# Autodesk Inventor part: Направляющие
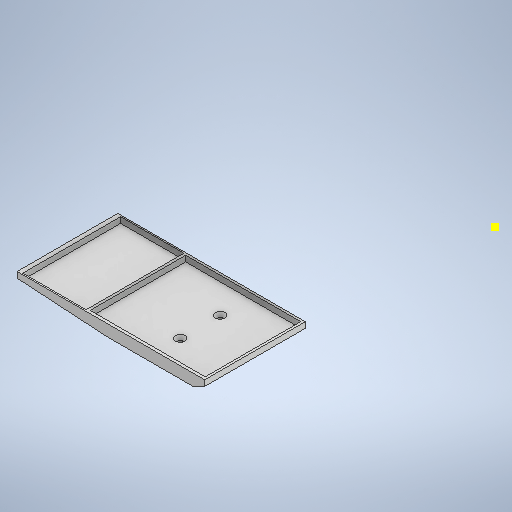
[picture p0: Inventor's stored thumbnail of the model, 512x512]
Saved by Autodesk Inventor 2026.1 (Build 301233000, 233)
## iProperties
Created: 2025-12
Part Number: Направляющие
Material: Типовые
Document SubType Name: Modeling
Designer: Yury Melnikov
Density: 1 g/cm^3
Appearance: По умолчанию
Author: Yury Melnikov
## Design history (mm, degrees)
sketch "Эскиз1"
  geometry: L1 (0, 0)-(16, 0); L2 (16, 0)-(16, -200); L3 (16, -200)-(0, -200); L4 (0, -200)-(0, 0); 1 further point
  constraints: 8 end point, 2 parallel, 1 coincident, 1 horizontal, 1 perpendicular
  dimensions: "d0" = 16 distance of L2.end L3.end; "d1" = 200 distance of L1.end L2.end
extrude "Выдавливание1" new body sketch "Эскиз1" distance "d2" = 200; taper "d3" = 0 deg
sketch "Эскиз2"
  geometry: 1 further point
sketch "Эскиз3"
  geometry: L1 (0, 0)-(0, -200) reference; L2 (-16, -200)-(-16, 0) reference; L3 (-28.3, -33.725)-(12.3, -10.284); L4 (12.3, -10.284)-(12.3, -57.165); L5 (12.3, -57.165)-(-28.3, -33.725); C1 r 12.3 at (-28.3, -33.725); C2 r 12.3 at (12.3, -10.284); C3 r 12.3 at (12.3, -57.165); 1 further point
  constraints: 6 end point, 3 centre point, 3 coincident, 2 equal radius, 2 tangent, 1 vertical, 7 other
  dimensions: "d4" = 24.6 diameter of C2
extrude "Выдавливание2" new body sketch "Эскиз3" distance "d5" = 11; taper "d6" = 0 deg
sketch "Эскиз4"
  geometry: C1 r 12.3 at (0, 0) reference; C2 r 12.3 at (40.6, 23.44) reference; C3 r 12.3 at (40.6, -23.44) reference; C4 r 4 at (0, 0); C5 r 4 at (40.6, 23.44); C6 r 4 at (40.6, -23.44); 1 further point
  constraints: 3 centre point, 3 coincident, 2 equal radius
  dimensions: "d7" = 8 diameter of C5
extrude "Выдавливание3" join sketch "Эскиз4" distance "d8" = 6; taper "d9" = 0 deg
sketch "Эскиз5"
  geometry: L1 (-6.15, 10.652)-(34.45, 34.093); L2 (52.9, 23.44)-(52.9, -23.44); L3 (34.45, -34.093)-(-6.15, -10.652); A1 r 12.3 centre (40.6, -23.44) between (34.45, -34.093) and (52.9, -23.44) reference; A2 r 12.3 centre (40.6, 23.44) between (52.9, 23.44) and (34.45, 34.093) reference; A3 r 12.3 centre (0, 0) between (-6.15, -10.652) and (-6.15, 10.652) reference; 1 further point
  constraints: 6 end point, 6 point on circle, 6 tangent
extrude "Выдавливание4" new body sketch "Эскиз5" distance "d10" = 4; taper "d11" = 0 deg
sketch "Эскиз6"
  geometry: L1 (0, 0)-(40.6, 23.44); L2 (40.6, 23.44)-(40.6, -23.44); L3 (40.6, -23.44)-(0, 0); L4 (35.6, 23.44)-(2.5, 4.33); L5 (2.5, -4.33)-(35.6, -23.44); L6 (43.1, -19.11)-(43.1, 19.11); L7 (38.1, 19.11)-(5, 0); L8 (5, 0)-(38.1, -19.11); L9 (38.1, -19.11)-(38.1, 19.11); C1 r 12.3 at (40.6, 23.44) reference; C2 r 12.3 at (40.6, -23.44) reference; C3 r 12.3 at (0, 0) reference; C4 r 1.6 at (0, 0); C5 r 1.6 at (40.6, 23.44); C6 r 1.6 at (40.6, -23.44); A1 r 5 centre (40.6, 23.44) between (43.1, 19.11) and (35.6, 23.44); A2 r 5 centre (0, 0) between (2.5, 4.33) and (2.5, -4.33); A3 r 5 centre (40.6, -23.44) between (35.6, -23.44) and (43.1, -19.11); 3 further points
  constraints: 18 end point, 8 coincident, 6 centre point, 6 point on circle, 2 equal length, 2 equal radius, 2 parallel, 13 other
  dimensions: "d12" = 2.5 distance between parallel lines of L1 L7; "d13" = 2.5 distance between parallel lines of L1 L4 (= d12); "d14" = 3.2 diameter of C4 (derived); "d15" = 3.2 diameter of C5 (derived); "d16" = 3.2 diameter of C6
extrude "Выдавливание5" join sketch "Эскиз6" distance "d17" = 5; taper "d18" = 0 deg
sketch "Эскиз7"
  geometry: C1 r 1.6 at (40.6, 23.44) reference; C2 r 1.6 at (0, 0) reference; C3 r 1.6 at (40.6, -23.44) reference; 1 further point
  node "Спроецированная петля5"
  node "Спроецированная петля6"
  node "Спроецированная петля7"
fillet "Сопряжение1" dims "d19" = 5
chamfer "Фаска1" distance "d20" = 2; stored, may be unused: second distance "d21" = 2, angle "d22" = 45 deg
extrude "Выдавливание6" cut sketch "Эскиз7" distance "d23" = 5; taper "d24" = 0 deg
sketch "Эскиз8"
  geometry: L1 (4.478, 5.472)-(33.622, 22.298) reference; L2 (43.1, 16.826)-(43.1, -16.826) reference; L3 (33.622, -22.298)-(4.478, -5.472) reference; L4 (34.45, 34.093)-(-6.15, 10.652) reference; L5 (-6.15, -10.652)-(34.45, -34.093) reference; L6 (52.9, -23.44)-(52.9, 23.44) reference; L7 (30, -82.992)-(34, -82.992); L8 (28.3, 33.725)-(28.3, -166.275) reference; L9 (142.9, -11.74)-(142.9, -38.74); L10 (139.9, -41.74)-(46.638, -41.74); L11 (35.571, -38.399)-(-6.806, -10.245); L12 (34.45, 34.093)-(-6.15, 10.652) reference; L13 (-6.15, 10.652)-(32.359, 35.974); L14 (141.217, -9.045)-(47.187, 36.917); A1 r 5 centre (1.978, -9.802) between (4.478, -5.472) and (0.989, -4.901) reference; A2 r 5 centre (0, 0) between (0.989, 4.901) and (0.989, -4.901) reference; A3 r 5 centre (1.978, 9.802) between (0.989, 4.901) and (4.478, 5.472) reference; A4 r 5 centre (31.122, 26.628) between (33.622, 22.298) and (35.861, 25.034) reference; A5 r 5 centre (40.6, 23.44) between (44.35, 20.133) and (35.861, 25.034) reference; A6 r 5 centre (48.1, 16.826) between (44.35, 20.133) and (43.1, 16.826) reference; A7 r 5 centre (48.1, -16.826) between (43.1, -16.826) and (44.35, -20.133) reference; A8 r 5 centre (40.6, -23.44) between (35.861, -25.034) and (44.35, -20.133) reference; A9 r 5 centre (31.122, -26.628) between (35.861, -25.034) and (33.622, -22.298) reference; A10 r 12.3 centre (40.6, 23.44) between (52.9, 23.44) and (34.45, 34.093) reference; A11 r 12.3 centre (0, 0) between (-6.15, 10.652) and (-6.15, -10.652) reference; A12 r 12.3 centre (40.6, -23.44) between (34.45, -34.093) and (52.9, -23.44) reference; A13 r 12.3 centre (0, 0) between (-6.15, 10.652) and (-6.15, -10.652) reference; A14 r 12.3 centre (40.6, 23.44) between (52.9, 23.44) and (34.45, 34.093) reference; A15 r 20 centre (46.638, -21.74) between (35.571, -38.399) and (46.638, -41.74); A16 r 3 centre (139.9, -11.74) between (142.9, -11.74) and (141.217, -9.045); A17 r 3 centre (139.9, -38.74) between (139.9, -41.74) and (142.9, -38.74); A18 r 15 centre (40.6, 23.44) between (26.541, 18.21) and (28.3, 14.855); A19 r 15 centre (40.6, 23.44) between (47.187, 36.917) and (32.359, 35.974); 6 further points
  constraints: 14 point on circle, 12 end point, 9 tangent, 7 point on line, 5 centre point, 1 coincident, 1 horizontal, 1 vertical, 1 vertical alignment
  dimensions: "d40" = 8 distance of point (142.9, -33.74) point (142.9, -41.74); "d41" = 90 distance from line of point (142.9, -41.74) L6; "d42" = 6 distance edge to line of A12 L10; "d43" = 20 radius of A15; "d44" = 3 radius of A16; "d45" = 3 radius of A17 (= d44); "d61" = 15 radius of A19; "d62" = 30 distance from line of L10 L9.start
extrude "Выдавливание7" new body sketch "Эскиз8" distance "d26" = 4; taper "d27" = 0 deg
node "РабПлоскость1"
sketch "Эскиз11"
  geometry: L1 (-6.806, -10.245)-(35.571, -38.399) reference; L2 (46.638, -41.74)-(139.9, -41.74) reference; L3 (142.9, -38.74)-(142.9, -11.74) reference; L4 (33.622, -22.298)-(4.478, -5.472) reference; L5 (4.478, 5.472)-(33.622, 22.298) reference; L6 (43.1, 16.826)-(43.1, -16.826) reference; L7 (30.967, -35.34)-(142.9, -35.34); L8 (37.92, -39.74)-(142.728, -39.74); L9 (77.92, -35.34)-(97.92, -35.34); L10 (97.92, -35.34)-(97.92, -39.74); L11 (97.92, -39.74)-(77.92, -39.74); L12 (77.92, -39.74)-(77.92, -35.34); L13 (112.9, -35.34)-(132.9, -35.34); L14 (132.9, -35.34)-(132.9, -39.74); L15 (132.9, -39.74)-(112.9, -39.74); L16 (112.9, -39.74)-(112.9, -35.34); L17 (32.359, 35.974)-(-6.15, 10.652) reference; L18 (141.217, -9.045)-(47.187, 36.917) reference; A1 r 12.3 centre (0, 0) between (-6.15, 10.652) and (-6.806, -10.245) reference; A2 r 20 centre (46.638, -21.74) between (35.571, -38.399) and (46.638, -41.74) reference; A3 r 3 centre (139.9, -38.74) between (139.9, -41.74) and (142.9, -38.74) reference; A4 r 3 centre (139.9, -11.74) between (142.9, -11.74) and (141.217, -9.045) reference; A5 r 5 centre (1.978, -9.802) between (4.478, -5.472) and (0.989, -4.901) reference; A6 r 5 centre (0, 0) between (0.989, 4.901) and (0.989, -4.901) reference; A7 r 5 centre (1.978, 9.802) between (0.989, 4.901) and (4.478, 5.472) reference; A8 r 5 centre (31.122, 26.628) between (33.622, 22.298) and (35.861, 25.034) reference; A9 r 5 centre (40.6, 23.44) between (44.35, 20.133) and (35.861, 25.034) reference; A10 r 5 centre (48.1, 16.826) between (44.35, 20.133) and (43.1, 16.826) reference; A11 r 5 centre (48.1, -16.826) between (43.1, -16.826) and (44.35, -20.133) reference; A12 r 5 centre (40.6, -23.44) between (35.861, -25.034) and (44.35, -20.133) reference; A13 r 5 centre (31.122, -26.628) between (35.861, -25.034) and (33.622, -22.298) reference; A14 r 15 centre (40.6, 23.44) between (47.187, 36.917) and (32.359, 35.974) reference; 1 further point
  constraints: 20 end point, 6 point on line, 4 horizontal, 4 parallel, 2 perpendicular, 2 point on circle
  dimensions: "d47" = 4.4 distance between parallel lines of L8 L7; "d48" = 2 distance between parallel lines of L2 L8; "d49" = 20 distance between parallel lines of L12 L10; "d50" = 20 distance between parallel lines of L14 L16; "d51" = 10 distance between parallel lines of L14 L3; "d52" = 40 distance from line of L8.start L12
extrude "Выдавливание9" cut sketch "Эскиз11" distance "d53" = 4; taper "d54" = 0 deg
chamfer "Фаска2" distance "d55" = 2; stored, may be unused: second distance "d56" = 2, angle "d57" = 45 deg
fillet "Сопряжение2" dims "d58" = 1
sketch "Эскиз14"
  geometry: L1 (-142.9, -35.34)-(-67.92, -35.34); L2 (-67.92, -35.34)-(-67.92, -39.74); L3 (-67.92, -39.74)-(-142.9, -39.74); L4 (-142.9, -39.74)-(-142.9, -35.34); L5 (-97.92, -35.34)-(-77.92, -35.34) reference; L6 (-77.92, -39.74)-(-97.92, -39.74) reference; L7 (-77.92, -35.34)-(-77.92, -39.74) reference; L8 (-142.9, -38.74)-(-142.9, -11.74) reference; 2 further points
  constraints: 8 end point, 3 collinear, 2 parallel, 1 horizontal, 1 midpoint, 1 perpendicular
  dimensions: "d63" = 10 distance from line of L2 point (-77.92, -37.54)
extrude "Выдавливание10" new body sketch "Эскиз14" distance "d65" = 228; taper "d66" = 0 deg
sketch "Эскиз15"
  geometry: L1 (3, 15)-(3, 11.4); L2 (3, 11.4)-(8, 6.4); L3 (8, 6.4)-(20, 6.4); L4 (20, 6.4)-(20, 3.4); L5 (20, 3.4)-(0, 3.4); L6 (0, 3.4)-(228, 3.4) reference; L7 (0, 3.4)-(0, 23); L8 (0, 23)-(20, 23); L9 (3, 15)-(8, 20); L10 (8, 20)-(20, 20); L11 (20, 20)-(20, 23); 5 further points; 1 other entity
  constraints: 20 end point, 4 equal length, 3 vertical, 2 horizontal, 2 perpendicular, 1 collinear, 1 other
  dimensions: "d67" = 3 distance of L3.end L4.end; "d76" = 3 distance between parallel lines of L7 L1 (derived); "d77" = 20 distance of L4.end L5.end; "d78" = 135 deg angle of L10 L9; "d79" = 5 horizontal distance of L1.start L9.end; "d108" = 4 distance of L7.end point (0, 27)
extrude "Выдавливание11" new body sketch "Эскиз15" stored distance "d69" = 128; taper "d70" = 0 deg
sketch "Эскиз16"
  geometry: L1 (67.92, -35.34)-(142.9, -35.34) reference; L2 (67.92, -39.74)-(67.92, -35.34) reference; L3 (142.9, -39.74)-(67.92, -39.74) reference; L4 (142.9, -35.34)-(142.9, -39.74) reference; L5 (132.9, -35.34)-(132.9, -39.74) reference; L6 (132.9, -39.74)-(112.9, -39.74) reference; L7 (112.9, -39.74)-(112.9, -35.34) reference; L8 (112.9, -35.34)-(132.9, -35.34) reference; L9 (97.92, -35.34)-(97.92, -39.74) reference; L10 (97.92, -39.74)-(77.92, -39.74) reference; L11 (77.92, -39.74)-(77.92, -35.34) reference; L12 (77.92, -35.34)-(97.92, -35.34) reference; L13 (-6.806, -10.245)-(35.571, -38.399) reference; L14 (46.638, -41.74)-(139.9, -41.74) reference; L15 (142.9, -38.74)-(142.9, -11.74) reference; L16 (141.217, -9.045)-(47.187, 36.917) reference; L17 (32.359, 35.974)-(-6.15, 10.652) reference; L18 (33.622, -22.298)-(4.478, -5.472) reference; L19 (4.478, 5.472)-(33.622, 22.298) reference; L20 (43.1, 16.826)-(43.1, -16.826) reference; L21 (97.72, -39.54)-(97.72, -35.54); L22 (97.72, -35.54)-(78.12, -35.54); L23 (78.12, -35.54)-(78.12, -39.54); L24 (78.12, -39.54)-(97.72, -39.54); L25 (113.1, -35.54)-(113.1, -39.54); L26 (113.1, -39.54)-(132.7, -39.54); L27 (132.7, -39.54)-(132.7, -35.54); L28 (132.7, -35.54)-(113.1, -35.54); A1 r 12.3 centre (0, 0) between (-6.15, 10.652) and (-6.806, -10.245) reference; A2 r 20 centre (46.638, -21.74) between (35.571, -38.399) and (46.638, -41.74) reference; A3 r 3 centre (139.9, -38.74) between (139.9, -41.74) and (142.9, -38.74) reference; A4 r 3 centre (139.9, -11.74) between (142.9, -11.74) and (141.217, -9.045) reference; A5 r 15 centre (40.6, 23.44) between (47.187, 36.917) and (32.359, 35.974) reference; A6 r 5 centre (1.978, -9.802) between (4.478, -5.472) and (0.989, -4.901) reference; A7 r 5 centre (0, 0) between (0.989, 4.901) and (0.989, -4.901) reference; A8 r 5 centre (1.978, 9.802) between (0.989, 4.901) and (4.478, 5.472) reference; A9 r 5 centre (31.122, 26.628) between (33.622, 22.298) and (35.861, 25.034) reference; A10 r 5 centre (40.6, 23.44) between (44.35, 20.133) and (35.861, 25.034) reference; A11 r 5 centre (48.1, 16.826) between (44.35, 20.133) and (43.1, 16.826) reference; A12 r 5 centre (48.1, -16.826) between (43.1, -16.826) and (44.35, -20.133) reference; A13 r 5 centre (40.6, -23.44) between (35.861, -25.034) and (44.35, -20.133) reference; A14 r 5 centre (31.122, -26.628) between (35.861, -25.034) and (33.622, -22.298) reference; 1 further point
  constraints: 16 end point, 6 other
  dimensions: "d71" = 0.2 distance between parallel lines of L9 L21; "d72" = 0.2 distance between parallel lines of L7 L25
extrude "Выдавливание12" join sketch "Эскиз16" stored distance "d73" = 228; taper "d74" = 0 deg
node "РабПлоскость2"
mirror "Зеркальное отражение2"
sketch "Эскиз17"
  geometry: L1 (15.8, 7.674)-(15.8, 4.326); L2 (15.8, 4.326)-(12.9, 2.651); L3 (12.9, 2.651)-(10, 4.326); L4 (10, 4.326)-(10, 7.674); L5 (10, 7.674)-(12.9, 9.349); L6 (12.9, 9.349)-(15.8, 7.674); L7 (12.9, 0.342)-(17.8, 3.171); L8 (17.8, 3.171)-(17.8, 8.829); L9 (17.8, 8.829)-(12.9, 11.658); L10 (12.9, 11.658)-(8, 8.829); L11 (8, 8.829)-(8, 3.171); L12 (8, 3.171)-(12.9, 0.342); L13 (0, 0)-(0, 12) reference; L14 (0, 17)-(74.98, 17) reference; L15 (32.59, 8.829)-(32.59, 3.171); L16 (34.59, 4.326)-(34.59, 7.674); L17 (37.49, 2.651)-(34.59, 4.326); L18 (37.49, 11.658)-(32.59, 8.829); L19 (32.59, 3.171)-(37.49, 0.342); L20 (34.59, 7.674)-(37.49, 9.349); L21 (40.39, 4.326)-(37.49, 2.651); L22 (40.39, 7.674)-(40.39, 4.326); L23 (37.49, 9.349)-(40.39, 7.674); L24 (37.49, 0.342)-(42.39, 3.171); L25 (42.39, 3.171)-(42.39, 8.829); L26 (42.39, 8.829)-(37.49, 11.658); L27 (57.18, 8.829)-(57.18, 3.171); L28 (59.18, 4.326)-(59.18, 7.674); L29 (62.08, 2.651)-(59.18, 4.326); L30 (62.08, 11.658)-(57.18, 8.829); L31 (57.18, 3.171)-(62.08, 0.342); L32 (59.18, 7.674)-(62.08, 9.349); L33 (64.98, 4.326)-(62.08, 2.651); L34 (64.98, 7.674)-(64.98, 4.326); L35 (62.08, 9.349)-(64.98, 7.674); L36 (62.08, 0.342)-(66.98, 3.171); L37 (66.98, 3.171)-(66.98, 8.829); L38 (66.98, 8.829)-(62.08, 11.658); L39 (74.98, 0)-(74.98, 12) reference; 11 further points
  constraints: 72 end point, 5 midpoint, 1 horizontal, 1 horizontal alignment, 1 vertical, 70 other
  dimensions: "d80" = 5.8 distance between parallel lines of L4 L1; "d82" = 2 distance from line of point (15.35, 1.756) L2; "d85" = 24.58984 distance of L10.end L15.start (derived); "d90" = 8 distance from line of point (8, 6) L13; "d157" = 8 distance of point (66.98, 6) point (74.98, 6) (derived)
extrude "Выдавливание13" join sketch "Эскиз17" distance "d92" = 2.5; taper "d93" = 0 deg
fillet "Сопряжение3" dims "d94" = 2
chamfer "Фаска3" distance "d95" = 0.8; stored, may be unused: second distance "d96" = 2, angle "d97" = 45 deg
sketch "Эскиз18"
  geometry: L1 (5.8, 3.349)-(2.9, 5.023) reference; L2 (2.9, 5.023)-(0, 3.349) reference; L3 (0, 3.349)-(0, 0) reference; L4 (0, 0)-(2.9, -1.674) reference; L5 (2.9, -1.674)-(5.8, 0) reference; L6 (5.8, 0)-(5.8, 3.349) reference; L7 (5.8, 3.349)-(5.8, 0) reference; L8 (-10, 7.674)-(64.98, 7.674) reference; C1 r 1.65 at (2.9, 1.674); C2 r 1.65 at (27.49, 1.674); C3 r 1.65 at (52.08, 1.674); C4 r 1.65 at (76.67, 1.674); 3 further points
  constraints: 4 centre point, 2 vertical alignment, 1 horizontal, 1 horizontal alignment, 1 midpoint, 6 other
  dimensions: "d98" = 3.3 diameter of C1; "d101" = 24.58984 distance of C1.centre C2.centre (derived)
extrude "Выдавливание14" cut sketch "Эскиз18" distance "d106" = 10; taper "d107" = 0 deg
node "РабПлоскость3"
mirror "Зеркальное отражение3"
sketch "Эскиз19"
  geometry: L1 (-97.72, -35.54)-(-97.72, -39.54) reference; L2 (-78.12, -35.54)-(-97.72, -35.54) reference; L3 (-78.12, -39.54)-(-78.12, -35.54) reference; L4 (-97.72, -39.54)-(-78.12, -39.54) reference; L5 (-77.92, -11.54)-(-97.92, -11.54); L6 (-97.92, -11.54)-(-97.92, -15.74); L7 (-97.92, -15.74)-(-77.92, -15.74); L8 (-77.92, -15.74)-(-77.92, -11.54); L9 (-142.9, -15.74)-(-67.92, -15.74) reference; L10 (-112.9, -11.54)-(-132.9, -11.54); L11 (-132.9, -11.54)-(-132.9, -15.74); L12 (-132.9, -15.74)-(-112.9, -15.74); L13 (-112.9, -15.74)-(-112.9, -11.54); L14 (-112.9, -39.74)-(-112.9, -35.34) reference; L15 (-132.9, -35.34)-(-132.9, -39.74) reference; L16 (-77.92, -39.74)-(-77.92, -35.34) reference; L17 (-97.92, -35.34)-(-97.92, -39.74) reference; 3 further points
  constraints: 16 end point, 6 collinear, 4 parallel, 2 horizontal, 2 perpendicular
  dimensions: "d109" = 4.2 distance of L7.end L5.start; "d110" = 4.2 distance of L12.end L10.start
extrude "Выдавливание15" cut sketch "Эскиз19" distance "d111" = 10; taper "d112" = 0 deg
sketch "Эскиз20"
  geometry: L1 (39.69, -35)-(35.29, -35); L2 (35.29, -35)-(35.29, -75); L3 (35.29, -75)-(39.69, -75); L4 (39.69, -75)-(39.69, -35); L5 (39.69, -94)-(35.29, -94); L6 (35.29, -94)-(35.29, -134); L7 (35.29, -134)-(39.69, -134); L8 (39.69, -134)-(39.69, -94); L9 (39.69, -153)-(35.29, -153); L10 (35.29, -153)-(35.29, -193); L11 (35.29, -193)-(39.69, -193); L12 (39.69, -193)-(39.69, -153); L13 (0, -20)-(74.98, -20) reference; L14 (0, 0)-(74.98, 0) reference; L15 (74.98, -228)-(0, -228) reference; 3 further points
  constraints: 24 end point, 2 midpoint, 2 parallel, 1 collinear, 1 horizontal, 1 perpendicular, 1 vertical, 1 vertical alignment, 15 other
  dimensions: "d113" = 4.4 distance of L1.start L1.end; "d116" = 59 distance of L1.start L5.start (derived); "d122" = 35 distance between parallel lines of L14 L1; "d123" = 35 distance from line of L15 L11.end; "d124" = 40 distance of L3.end L1.start
extrude "Выдавливание16" cut sketch "Эскиз20" distance "d125" = 10; taper "d126" = 0 deg
sketch "Эскиз21"
  geometry: L1 (39.69, -193)-(35.29, -193) reference; L2 (35.29, -193)-(35.29, -153) reference; L3 (35.29, -153)-(39.69, -153) reference; L4 (39.69, -153)-(39.69, -193) reference; L5 (39.69, -134)-(35.29, -134) reference; L6 (35.29, -134)-(35.29, -94) reference; L7 (35.29, -94)-(39.69, -94) reference; L8 (39.69, -94)-(39.69, -134) reference; L9 (39.69, -75)-(35.29, -75) reference; L10 (35.29, -75)-(35.29, -35) reference; L11 (35.29, -35)-(39.69, -35) reference; L12 (39.69, -35)-(39.69, -75) reference; L13 (74.98, 0)-(0, 0) reference; L14 (0, 0)-(0, -228) reference; L15 (74.98, -228)-(0, -228) reference; L16 (74.98, 0)-(74.98, -228) reference; L17 (39.59, -74.9)-(35.39, -74.9); L18 (35.39, -74.9)-(35.39, -35.1); L19 (35.39, -35.1)-(39.59, -35.1); L20 (39.59, -35.1)-(39.59, -74.9); L21 (39.59, -133.9)-(35.39, -133.9); L22 (35.39, -133.9)-(35.39, -94.1); L23 (35.39, -94.1)-(39.59, -94.1); L24 (39.59, -94.1)-(39.59, -133.9); L25 (39.59, -192.9)-(35.39, -192.9); L26 (35.39, -192.9)-(35.39, -153.1); L27 (35.39, -153.1)-(39.59, -153.1); L28 (39.59, -153.1)-(39.59, -192.9); L29 (0, -20)-(74.98, -20) reference; L30 (39.59, -20)-(35.39, -20); L31 (35.39, -20)-(35.39, -208); L32 (35.39, -208)-(39.59, -208); L33 (39.59, -208)-(39.59, -20); C1 r 1.65 at (62.08, -14) reference; C2 r 1.65 at (37.49, -14) reference; C3 r 1.65 at (12.9, -14) reference; 1 further point
  constraints: 32 end point, 2 collinear, 2 parallel, 1 horizontal, 1 perpendicular, 1 point on line, 9 other
  dimensions: "d127" = 0.1 distance between parallel lines of L12 L20; "d128" = 0.1 distance between parallel lines of L8 L24; "d129" = 0.1 distance between parallel lines of L4 L28; "d130" = 20 distance between parallel lines of L15 L32
extrude "Выдавливание17" new body sketch "Эскиз21" stored distance "d131" = 10; taper "d132" = 0 deg
sketch "Эскиз22"
  geometry: L1 (39.59, -20)-(35.39, -20); L2 (35.39, -20)-(35.39, -208); L3 (35.39, -208)-(39.59, -208); L4 (39.59, -208)-(39.59, -20); L5 (0, -20)-(74.98, -20) reference; L6 (74.98, -228)-(0, -228) reference; 3 further points
  constraints: 8 end point, 2 parallel, 2 point on line, 1 collinear, 1 horizontal, 1 perpendicular
  dimensions: "d133" = 20 distance between parallel lines of L6 L3
extrude "Выдавливание18" join sketch "Эскиз22" stored distance "d134" = 10; taper "d135" = 0 deg
node "РабПлоскость4"
mirror "Зеркальное отражение4"
sketch "Эскиз23"
  geometry: L1 (-112.9, -15.74)-(-132.9, -15.74) reference; L2 (-132.9, -15.74)-(-132.9, -11.54) reference; L3 (-132.9, -11.54)-(-112.9, -11.54) reference; L4 (-112.9, -11.54)-(-112.9, -15.74) reference; L5 (-77.92, -15.74)-(-97.92, -15.74) reference; L6 (-97.92, -15.74)-(-97.92, -11.54) reference; L7 (-97.92, -11.54)-(-77.92, -11.54) reference; L8 (-77.92, -11.54)-(-77.92, -15.74) reference; L9 (-132.9, -39.74)-(-132.9, -35.34) reference; L10 (-132.9, -35.34)-(-112.9, -35.34) reference; L11 (-112.9, -35.34)-(-112.9, -39.74) reference; L12 (-112.9, -39.74)-(-132.9, -39.74) reference; L13 (-97.92, -39.74)-(-97.92, -35.34) reference; L14 (-97.92, -35.34)-(-77.92, -35.34) reference; L15 (-77.92, -35.34)-(-77.92, -39.74) reference; L16 (-77.92, -39.74)-(-97.92, -39.74) reference; L17 (-32.359, 35.974)-(6.15, 10.652) reference; L18 (-141.217, -9.045)-(-47.187, 36.917) reference; L19 (-142.9, -38.74)-(-142.9, -11.74) reference; L20 (-46.638, -41.74)-(-139.9, -41.74) reference; L21 (6.806, -10.245)-(-35.571, -38.399) reference; L22 (-33.622, -22.298)-(-4.478, -5.472) reference; L23 (-43.1, 16.826)-(-43.1, -16.826) reference; L24 (-4.478, 5.472)-(-33.622, 22.298) reference; C1 r 1.65 at (-45.173, -38.366); C2 r 1.65 at (-57.173, -38.366); C3 r 12.3 at (-40.6, -23.44) reference; C4 r 3.31 at (-45.173, -38.366); A1 r 12.3 centre (0, 0) between (6.806, -10.245) and (6.15, 10.652) reference; A2 r 15 centre (-40.6, 23.44) between (-32.359, 35.974) and (-47.187, 36.917) reference; A3 r 3 centre (-139.9, -11.74) between (-141.217, -9.045) and (-142.9, -11.74) reference; A4 r 3 centre (-139.9, -38.74) between (-142.9, -38.74) and (-139.9, -41.74) reference; A5 r 20 centre (-46.638, -21.74) between (-46.638, -41.74) and (-35.571, -38.399) reference; A6 r 5 centre (-31.122, -26.628) between (-33.622, -22.298) and (-35.861, -25.034) reference; A7 r 5 centre (-40.6, -23.44) between (-44.35, -20.133) and (-35.861, -25.034) reference; A8 r 5 centre (-48.1, -16.826) between (-44.35, -20.133) and (-43.1, -16.826) reference; A9 r 5 centre (-48.1, 16.826) between (-43.1, 16.826) and (-44.35, 20.133) reference; A10 r 5 centre (-40.6, 23.44) between (-35.861, 25.034) and (-44.35, 20.133) reference; A11 r 5 centre (-31.122, 26.628) between (-35.861, 25.034) and (-33.622, 22.298) reference; A12 r 5 centre (-1.978, 9.802) between (-4.478, 5.472) and (-0.989, 4.901) reference; A13 r 5 centre (0, 0) between (-0.989, -4.901) and (-0.989, 4.901) reference; A14 r 5 centre (-1.978, -9.802) between (-0.989, -4.901) and (-4.478, -5.472) reference; 1 further point
  constraints: 3 centre point, 2 tangent, 1 coincident, 1 equal radius, 1 horizontal alignment
  dimensions: "d136" = 3.3 diameter of C2; "d137" = 12 distance of C1.centre C2.centre
extrude "Выдавливание19" cut sketch "Эскиз23" distance "d138" = 10; taper "d139" = 0 deg
sketch "Эскиз24"
  geometry: C1 r 4 at (0, 0) reference; C2 r 4 at (40.6, 23.44) reference; C3 r 4 at (40.6, -23.44) reference; C4 r 2.5 at (0, 0); C5 r 2.5 at (40.6, 23.44); C6 r 2.5 at (40.6, -23.44); C7 r 5.5 at (40.6, 23.44); C8 r 5.5 at (0, 0); C9 r 5.5 at (40.6, -23.44); 1 further point
  constraints: 6 centre point, 2 coincident, 1 concentric
  dimensions: "d140" = 5 diameter of C4; "d141" = 5 diameter of C5; "d142" = 5 diameter of C6; "d143" = 3 radial gap between concentric circles of C5 C7; "d144" = 3 radial gap between concentric circles of C4 C8; "d145" = 3 radial gap between concentric circles of C6 C9
extrude "Выдавливание20" join sketch "Эскиз24" stored distance "d146" = 10; taper "d147" = 0 deg
sketch "Эскиз25"
  geometry: C1 r 5.5 at (0, 0) reference; C2 r 5.5 at (40.6, -23.44) reference; C3 r 5.5 at (40.6, 23.44) reference; C4 r 2.5 at (0, 0); C5 r 2.5 at (40.6, 23.44); C6 r 2.5 at (40.6, -23.44); 1 further point
  constraints: 3 centre point, 3 coincident, 2 equal radius
  dimensions: "d148" = 5 diameter of C4
extrude "Выдавливание21" cut sketch "Эскиз25" distance "d149" = 30; taper "d150" = 0 deg
chamfer "Фаска4" distance "d151" = 4; stored, may be unused: second distance "d152" = 2, angle "d153" = 45 deg
sketch "Эскиз26"
  geometry: L1 (39.69, -193)-(35.29, -193) reference; L2 (35.29, -193)-(35.29, -153) reference; L3 (35.29, -153)-(39.69, -153) reference; L4 (39.69, -153)-(39.69, -193) reference; L5 (39.69, -134)-(35.29, -134) reference; L6 (35.29, -134)-(35.29, -94) reference; L7 (35.29, -94)-(39.69, -94) reference; L8 (39.69, -94)-(39.69, -134) reference; L9 (39.69, -75)-(35.29, -75) reference; L10 (35.29, -75)-(35.29, -35) reference; L11 (35.29, -35)-(39.69, -35) reference; L12 (39.69, -35)-(39.69, -75) reference; L13 (74.98, 0)-(0, 0) reference; L14 (0, 0)-(0, -228) reference; L15 (74.98, -228)-(0, -228) reference; L16 (74.98, 0)-(74.98, -228) reference; L17 (74.98, 0)-(64.78, 0); L18 (64.78, 0)-(64.78, -5); L19 (64.78, -5)-(74.98, -5); L20 (74.98, -5)-(74.98, 0); L21 (64.78, 0)-(64.78, 4) reference; L22 (74.98, -228)-(64.78, -228); L23 (64.78, -228)-(64.78, -223); L24 (64.78, -223)-(74.98, -223); L25 (74.98, -223)-(74.98, -228); L26 (64.78, -228)-(64.78, -232) reference; C1 r 1.65 at (62.08, -14) reference; C2 r 1.65 at (37.49, -14) reference; C3 r 1.65 at (12.9, -14) reference; 5 further points
  constraints: 16 end point, 4 parallel, 3 collinear, 2 horizontal, 2 perpendicular
  dimensions: "d154" = 5 distance of L18.end L17.end
extrude "Выдавливание22" cut sketch "Эскиз26" distance "d155" = 30; taper "d156" = 0 deg
feature "Толщина1" dims "d158" = 0.2, "d159" = 0.2
sketch "Эскиз27"
  geometry: L1 (-16.475, -18.345)-(-16.475, 18.345); L2 (-16.475, 18.345)-(-48.25, 0); L3 (-48.25, 0)-(-16.475, -18.345); L4 (-52.9, -23.44)-(-52.9, 23.44) reference; L5 (6.15, -10.652)-(-34.45, -34.093) reference; L6 (-34.45, 34.093)-(6.15, 10.652) reference; C1 r 1.65 at (-16.475, 18.345); C2 r 1.65 at (-16.475, -18.345); C3 r 1.65 at (-48.25, 0); 1 further point
  constraints: 6 end point, 3 centre point, 2 equal length, 2 equal radius, 1 vertical
  dimensions: "d160" = 3.3 diameter of C2; "d161" = 3 distance edge to line of C3 L4; "d162" = 3 distance edge to line of C2 L5; "d163" = 3 distance edge to line of C1 L6
extrude "Выдавливание23" cut sketch "Эскиз27" distance "d164" = 20; taper "d165" = 0 deg
chamfer "Фаска5" distance "d166" = 2; stored, may be unused: second distance "d167" = 2, angle "d168" = 45 deg
sketch "Эскиз28"
  geometry: L1 (14.517, 4.6)-(16.133, 1.8); L2 (16.133, 1.8)-(14.517, -1); L3 (14.517, -1)-(11.283, -1); L4 (11.283, -1)-(9.667, 1.8); L5 (9.667, 1.8)-(11.283, 4.6); L6 (11.283, 4.6)-(14.517, 4.6); L7 (0, 0)-(0, 3.6) reference; L8 (13.9, 6.1)-(11.9, 6.1) reference; L9 (39.106, 4.6)-(40.723, 1.8); L10 (40.723, 1.8)-(39.106, -1); L11 (39.106, -1)-(35.873, -1); L12 (35.873, -1)-(34.257, 1.8); L13 (34.257, 1.8)-(35.873, 4.6); L14 (35.873, 4.6)-(39.106, 4.6); L15 (63.696, 4.6)-(65.313, 1.8); L16 (65.313, 1.8)-(63.696, -1); L17 (63.696, -1)-(60.463, -1); L18 (60.463, -1)-(58.847, 1.8); L19 (58.847, 1.8)-(60.463, 4.6); L20 (60.463, 4.6)-(63.696, 4.6); L21 (38.49, 6.1)-(36.49, 6.1) reference; L22 (17.981, 1.8)-(15.44, 6.2); L23 (15.44, 6.2)-(10.36, 6.2); L24 (10.36, 6.2)-(7.819, 1.8); L25 (7.819, 1.8)-(10.36, -2.6); L26 (10.36, -2.6)-(15.44, -2.6); L27 (15.44, -2.6)-(17.981, 1.8); L28 (34.949, 6.2)-(32.409, 1.8); L29 (32.409, 1.8)-(34.949, -2.6); L30 (34.949, -2.6)-(40.03, -2.6); L31 (40.03, -2.6)-(42.571, 1.8); L32 (42.571, 1.8)-(40.03, 6.2); L33 (40.03, 6.2)-(34.949, 6.2); L34 (59.539, 6.2)-(56.999, 1.8); L35 (56.999, 1.8)-(59.539, -2.6); L36 (59.539, -2.6)-(64.62, -2.6); L37 (64.62, -2.6)-(67.16, 1.8); L38 (67.16, 1.8)-(64.62, 6.2); L39 (64.62, 6.2)-(59.539, 6.2); 7 further points
  constraints: 72 end point, 3 midpoint, 2 horizontal, 2 vertical alignment, 1 collinear, 1 horizontal alignment, 53 other
  dimensions: "d169" = 5.6 distance between parallel lines of L3 L6; "d172" = 24.58984 distance of point (12.9, 1.8) point (37.49, 1.8) (derived); "d177" = 1.6 distance between parallel lines of L1 L22; "d178" = 1.6 distance between parallel lines of L13 L28; "d179" = 1.6 distance between parallel lines of L19 L34
extrude "Выдавливание24" join sketch "Эскиз28" distance "d180" = 3; taper "d181" = 0 deg
sketch "Эскиз29"
  geometry: L1 (15.44, 6.2)-(10.36, 6.2) reference; L2 (10.36, 6.2)-(7.819, 1.8) reference; L3 (7.819, 1.8)-(10.36, -2.6) reference; L4 (10.36, -2.6)-(15.44, -2.6) reference; L5 (15.44, -2.6)-(17.981, 1.8) reference; L6 (17.981, 1.8)-(15.44, 6.2) reference; L7 (14.517, 4.6)-(16.133, 1.8) reference; L8 (16.133, 1.8)-(14.517, -1) reference; L9 (14.517, -1)-(11.283, -1) reference; L10 (11.283, -1)-(9.667, 1.8) reference; L11 (9.667, 1.8)-(11.283, 4.6) reference; L12 (11.283, 4.6)-(14.517, 4.6) reference; L13 (32.409, 1.8)-(34.949, -2.6) reference; L14 (34.949, -2.6)-(40.03, -2.6) reference; L15 (40.03, -2.6)-(42.571, 1.8) reference; L16 (42.571, 1.8)-(40.03, 6.2) reference; L17 (40.03, 6.2)-(34.949, 6.2) reference; L18 (34.949, 6.2)-(32.409, 1.8) reference; L19 (39.106, 4.6)-(40.723, 1.8) reference; L20 (40.723, 1.8)-(39.106, -1) reference; L21 (39.106, -1)-(35.873, -1) reference; L22 (35.873, -1)-(34.257, 1.8) reference; L23 (34.257, 1.8)-(35.873, 4.6) reference; L24 (35.873, 4.6)-(39.106, 4.6) reference; L25 (56.999, 1.8)-(59.539, -2.6) reference; L26 (59.539, -2.6)-(64.62, -2.6) reference; L27 (64.62, -2.6)-(67.16, 1.8) reference; L28 (67.16, 1.8)-(64.62, 6.2) reference; L29 (64.62, 6.2)-(59.539, 6.2) reference; L30 (59.539, 6.2)-(56.999, 1.8) reference; L31 (63.696, 4.6)-(65.313, 1.8) reference; L32 (65.313, 1.8)-(63.696, -1) reference; L33 (63.696, -1)-(60.463, -1) reference; L34 (60.463, -1)-(58.847, 1.8) reference; L35 (58.847, 1.8)-(60.463, 4.6) reference; L36 (60.463, 4.6)-(63.696, 4.6) reference; 1 further point
extrude "Выдавливание25" cut sketch "Эскиз29" stored distance "d182" = 3; taper "d183" = 0 deg
sketch "Эскиз30"
  geometry: L1 (-24.59, 5.6)-(-26.206, 2.8) reference; L2 (-24.59, 0)-(-26.206, 2.8) reference; L3 (-21.357, 0)-(-24.59, 0) reference; L4 (-21.357, 0)-(-19.74, 2.8) reference; L5 (-19.74, 2.8)-(-21.357, 5.6) reference; L6 (-24.59, 5.6)-(-21.357, 5.6) reference; L7 (0, 5.6)-(-1.617, 2.8) reference; L8 (0, 0)-(-1.617, 2.8) reference; L9 (3.233, 0)-(0, 0) reference; L10 (3.233, 0)-(4.85, 2.8) reference; L11 (4.85, 2.8)-(3.233, 5.6) reference; L12 (0, 5.6)-(3.233, 5.6) reference; L13 (24.59, 5.6)-(22.973, 2.8) reference; L14 (24.59, 0)-(22.973, 2.8) reference; L15 (27.823, 0)-(24.59, 0) reference; L16 (27.823, 0)-(29.44, 2.8) reference; L17 (29.44, 2.8)-(27.823, 5.6) reference; L18 (24.59, 5.6)-(27.823, 5.6) reference; L19 (24.59, 5.6)-(27.823, 5.6) reference; L20 (0, 5.6)-(3.233, 5.6) reference; L21 (-24.59, 5.6)-(-21.357, 5.6) reference; C1 r 1.65 at (-22.973, 2.8); C2 r 1.65 at (1.617, 2.8); C3 r 1.65 at (26.206, 2.8); 4 further points
  constraints: 3 centre point, 3 horizontal alignment, 3 midpoint, 3 vertical alignment, 2 equal radius
  dimensions: "d184" = 3.3 diameter of C2
extrude "Выдавливание26" cut sketch "Эскиз30" distance "d185" = 10; taper "d186" = 0 deg
chamfer "Фаска6" distance "d187" = 0.7; stored, may be unused: second distance "d188" = 2, angle "d189" = 45 deg
fillet "Сопряжение4" dims "d190" = 1
sketch "Эскиз31"
  geometry: L1 (19.6, -236)-(0, -236) reference; L2 (0, -232)-(0, -236) reference; L3 (19.6, -232)-(0, -232) reference; L4 (19.6, -232)-(19.6, -236) reference; L5 (54.58, -236)-(34.98, -236) reference; L6 (34.98, -232)-(34.98, -236) reference; L7 (54.58, -232)-(34.98, -232) reference; L8 (54.58, -232)-(54.58, -236) reference; L9 (19.6, 0)-(0, 0) reference; L10 (19.6, -4)-(19.6, 0) reference; L11 (0, -4)-(19.6, -4) reference; L12 (0, -4)-(0, 0) reference; L13 (54.58, 0)-(34.98, 0) reference; L14 (54.58, -4)-(54.58, 0) reference; L15 (34.98, -4)-(54.58, -4) reference; L16 (34.98, -4)-(34.98, 0) reference; 1 further point
extrude "Выдавливание27" join sketch "Эскиз31" stored distance "d191" = 10; taper "d192" = 0 deg
mirror "Зеркальное отражение5"
chamfer "Фаска7" distance "d193" = 0.5; stored, may be unused: second distance "d194" = 2, angle "d195" = 45 deg
sketch "Эскиз32"
  geometry: L1 (-52.9, -23.44)-(-51.9, -23.44) reference; L2 (-52.9, -23.44)-(-52.9, 23.44) reference; L3 (6.15, -10.652)-(-34.45, -34.093) reference; L4 (-34.45, 34.093)-(6.15, 10.652) reference; C1 r 3.65 at (-16.475, -18.345) reference; C2 r 1.6 at (-40.6, 23.44) reference; C3 r 1.6 at (-40.6, -23.44) reference; C4 r 1.6 at (0, 0) reference; C5 r 3.65 at (-16.475, 18.345) reference; C6 r 3.65 at (-48.25, 0) reference; A1 r 35 centre (-27.005, 0.107) between (-52.9, -23.44) and (-34.45, -34.093); A2 r 12.3 centre (-40.6, 23.44) between (-34.45, 34.093) and (-52.9, 23.44) reference; A3 r 12.3 centre (-40.6, -23.44) between (-52.9, -23.44) and (-34.45, -34.093) reference; A4 r 12.3 centre (0, 0) between (6.15, -10.652) and (6.15, 10.652) reference; 3 further points
  constraints: 2 point on circle, 1 centre point
  dimensions: "d196" = 35 radius of A1
extrude "Выдавливание28" cut sketch "Эскиз32" distance "d197" = 10; taper "d198" = 0 deg
fillet "Сопряжение5" dims "d199" = 10
chamfer "Фаска8" distance "d200" = 1; stored, may be unused: second distance "d201" = 2, angle "d202" = 45 deg
sketch "Эскиз33"
  geometry: C1 r 1.6 at (-40.6, 23.44) reference; C2 r 1.65 at (-40.6, 23.44); C3 r 4.05 at (-40.6, 23.44); 1 further point
  constraints: 2 centre point, 1 coincident
  dimensions: "d203" = 3.3 diameter of C2; "d204" = 2.4 radial gap between concentric circles of C2 C3
extrude "Выдавливание29" new body sketch "Эскиз33" distance "d205" = 5; taper "d206" = 0 deg
sketch "Эскиз34"
  geometry: C1 r 1.65 at (0, 0) reference; C2 r 2.45 at (0, 0); 1 further point
  constraints: 1 centre point
  dimensions: "d207" = 0.8 radial gap between concentric circles of C1 C2
extrude "Выдавливание30" join sketch "Эскиз34" distance "d208" = 1; taper "d209" = 0 deg
chamfer "Фаска10" distance "d213" = 0.5; stored, may be unused: second distance "d214" = 1.6, angle "d215" = 45 deg
sketch "Эскиз35"
  geometry: C1 r 12.3 at (0, 0) reference; C2 r 1.65 at (0, 0); 1 further point
  constraints: 1 centre point, 1 coincident
  dimensions: "d216" = 3.3 diameter of C2
extrude "Выдавливание31" new body sketch "Эскиз35" distance "d217" = 11; taper "d218" = 0 deg
sketch "Эскиз36"
  geometry: L1 (-2.8, -1.617)-(-2.8, 1.617); L2 (-2.8, 1.617)-(0, 3.233); L3 (0, 3.233)-(2.8, 1.617); L4 (2.8, 1.617)-(2.8, -1.617); L5 (2.8, -1.617)-(0, -3.233); L6 (0, -3.233)-(-2.8, -1.617); C1 r 1.65 at (0, 0) reference; 2 further points
  constraints: 12 end point, 1 coincident, 1 vertical, 13 other
  dimensions: "d219" = 5.6 distance between parallel lines of L4 L1
extrude "Выдавливание32" cut sketch "Эскиз36" distance "d220" = 5; taper "d221" = 0 deg
fillet "Сопряжение6" dims "d225" = 1
sketch "Эскиз38"
  geometry: C1 r 1.65 at (0, 0) reference; C2 r 3.9 at (0, 0); 1 further point
  constraints: 1 centre point, 1 coincident
  dimensions: "d230" = 7.8 diameter of C2
extrude "Выдавливание33" cut sketch "Эскиз38" stored distance "d231" = 4; taper "d232" = 0 deg
chamfer "Фаска12" distance "d233" = 0.4; stored, may be unused: second distance "d234" = 1.6, angle "d235" = 45 deg
sketch "Эскиз40"
  geometry: C1 r 1.6 at (0, 0) reference; C2 r 1.6 at (-40.6, -23.44) reference; 3 further points
  constraints: 2 coincident
feature "Массив по эскизу1" sketch "Эскиз40"
sketch "Эскиз41"
  geometry: C1 r 1.6 at (0, 0) reference; C2 r 1.6 at (-40.6, -23.44) reference; 3 further points
  constraints: 2 coincident
feature "Массив по эскизу2" sketch "Эскиз41"
mirror "Зеркальное отражение6"
mirror "Зеркальное отражение7"
mirror "Зеркальное отражение8"
mirror "Зеркальное отражение9"
mirror "Зеркальное отражение10"
node "РабПлоскость6"
mirror "Зеркальное отражение11"
sketch "Эскиз42"
  geometry: L1 (4.2, -55)-(-23.8, -55); L2 (-23.8, -55)-(-23.8, -90.855); L3 (-23.8, -90.855)-(4.2, -90.855); L4 (4.2, -90.855)-(4.2, -55); L5 (-29.8, 0)-(-29.8, -228) reference; L6 (9.89, -75)-(5.49, -75) reference; C1 r 1.75 at (4.2, -55); C2 r 1.75 at (4.2, -90.855); C3 r 1.75 at (-23.8, -55); C4 r 1.75 at (-23.8, -90.855); 1 further point
  constraints: 8 end point, 4 centre point, 2 horizontal, 2 parallel, 1 perpendicular, 1 vertical, 6 other
  dimensions: "d237" = 35.855 distance of L1.end L2.end; "d238" = 28 distance of L1.start L1.end; "d239" = 3.5 diameter of C1; "d240" = 6 distance from line of L5 L1.end; "d241" = 20 distance from line of L1.start L6; "d244" = 35.855 distance of L1.start C2.centre (derived); "d247" = 28 distance of L1.start C3.centre (derived)
extrude "Выдавливание34" cut sketch "Эскиз42" distance "d250" = 10; taper "d251" = 0 deg
chamfer "Фаска13" distance "d252" = 2; stored, may be unused: second distance "d253" = 2, angle "d254" = 45 deg
sketch "Эскиз43"
  geometry: L1 (45.18, -5)-(45.18, -223) reference; L2 (-29.8, 0)-(-29.8, -228) reference; L3 (45.18, -116.855)-(-29.8, -116.855); L4 (-29.8, -116.855)-(-29.8, -227); L5 (-29.8, -227)-(45.18, -227); L6 (45.18, -227)-(45.18, -116.855); L7 (-28.117, -228)-(65.913, -228) reference; C1 r 1.75 at (-23.8, -90.855) reference; 1 further point
  constraints: 8 end point, 2 parallel, 2 point on line, 1 horizontal, 1 perpendicular
  dimensions: "d255" = 1 distance between parallel lines of L7 L5; "d256" = 26 distance from line of C1.centre L3
node "РабПлоскость7"
sketch "Эскиз44"
  geometry: L1 (-52.526, -130.428)-(-106.526, -130.428); L2 (-106.526, -130.428)-(-106.526, -214.428); L3 (-106.526, -214.428)-(-52.526, -214.428); L4 (-52.526, -214.428)-(-52.526, -130.428); L5 (41.041, -116.855)-(41.041, -228); L6 (-28.117, -228)-(65.913, -228) reference; L7 (60.2, -208)-(60.2, -217) reference; L8 (52.474, -130.928)-(-47.526, -130.928); L9 (-47.526, -130.928)-(-47.526, -213.928); L10 (-47.526, -213.928)-(52.474, -213.927); L11 (52.474, -213.927)-(52.474, -130.928); L12 (45.18, -116.855)-(54.474, -127.928); L13 (54.474, -127.928)-(54.474, -215.927); L14 (54.474, -215.927)-(45.18, -227); L15 (-108.526, -128.428)-(-108.526, -219.266); L16 (-108.526, -128.428)-(54.474, -128.428); L17 (-108.526, -215.927)-(54.474, -215.927); 6 further points
  constraints: 30 end point, 4 horizontal, 4 midpoint, 4 parallel, 3 point on line, 2 horizontal alignment, 2 perpendicular, 2 vertical, 1 equal length
  dimensions: "d258" = 54 distance of L3.end L2.end; "d259" = 84 distance of L2.end L1.end; "d261" = 100 distance of L10.end L9.end; "d262" = 83 distance of L9.end L8.end; "d264" = 5 distance between parallel lines of L9 L4; "d265" = 2 distance between parallel lines of L13 L11; "d266" = 2 distance from line of L13.end L10; "d268" = 2 distance from line of L1 L15.start; "d290" = 2 distance between parallel lines of L15 L2
feature "Лофт1" sketch "Эскиз44" dims "d269" = 0, "d270" = 90 deg, "d291" = 0, "d292" = 90 deg
sketch "Эскиз45"
  geometry: L1 (84.274, -99.072)-(84.274, -11.573) reference; L2 (-75, -12.822)-(-20, -12.823); L3 (-20, -12.823)-(-20, -97.823); L4 (-20, -97.823)-(-75, -97.823); L5 (-75, -97.823)-(-75, -12.822); L6 (82.274, -13.573)-(-17.726, -13.573); L7 (-17.726, -13.573)-(-17.726, -96.573); L8 (-17.726, -96.573)-(82.274, -96.573); L9 (82.274, -96.573)-(82.274, -13.573); L10 (84.274, -99.072)-(84.274, -11.573) reference; L11 (-78.726, -99.072)-(84.274, -99.072) reference; L12 (-78.726, -11.573)-(-78.726, -99.072) reference; L13 (84.274, -11.573)-(-78.726, -11.573) reference; 7 further points
  constraints: 16 end point, 4 parallel, 3 midpoint, 2 horizontal, 2 horizontal alignment, 2 perpendicular, 1 point on line
  dimensions: "d273" = 55 distance of L3.end L4.end; "d274" = 85 distance of L2.end L3.end; "d276" = 100 distance of L8.end L7.end; "d277" = 83 distance of L7.end L6.end; "d278" = 2 distance between parallel lines of L1 L9
extrude "Выдавливание35" join sketch "Эскиз45" distance "d279" = 5; taper "d280" = 0 deg
sketch "Эскиз46"
  geometry: L1 (82.506, 125.427)-(82.506, 134.427) reference; L2 (82.506, 134.427)-(62.906, 134.427) reference; L3 (62.906, 134.427)-(62.906, 130.428) reference; L4 (47.526, 130.428)-(62.906, 130.428) reference; L5 (47.526, 130.428)-(47.526, 134.427) reference; L6 (47.526, 134.427)-(27.926, 134.427) reference; L7 (27.926, 134.427)-(27.926, 130.428) reference; L8 (17.726, 130.428)-(27.926, 130.428) reference; L9 (17.726, 130.428)-(17.726, -97.573) reference; L10 (17.726, -97.573)-(27.926, -97.573) reference; L11 (27.926, -97.573)-(27.926, -101.572) reference; L12 (27.926, -101.572)-(47.526, -101.572) reference; L13 (47.526, -101.572)-(47.526, -97.573) reference; L14 (47.526, -97.573)-(62.906, -97.573) reference; L15 (62.906, -97.573)-(62.906, -101.572) reference; L16 (62.906, -101.572)-(82.506, -101.572) reference; L17 (82.506, -101.572)-(82.506, -92.573) reference; L18 (82.506, -92.573)-(92.706, -92.573) reference; L19 (92.706, 125.427)-(92.706, -92.573) reference; L20 (92.706, 125.427)-(82.506, 125.427) reference; L21 (53.016, 76.61)-(53.016, 95.427) reference; L22 (53.016, 95.427)-(57.416, 95.427) reference; L23 (57.416, 95.427)-(57.416, 55.427) reference; L24 (57.416, 55.427)-(53.016, 55.427) reference; L25 (53.016, 55.427)-(53.016, 74.245) reference; L26 (53.016, -3.573)-(53.016, 36.427) reference; L27 (53.016, 36.427)-(57.416, 36.427) reference; L28 (57.416, 36.427)-(57.416, -3.573) reference; L29 (57.416, -3.573)-(53.016, -3.573) reference; L30 (57.416, -62.573)-(53.016, -62.573) reference; L31 (53.016, -62.573)-(53.016, -22.573) reference; L32 (53.016, -22.573)-(57.416, -22.573) reference; L33 (57.416, -22.573)-(57.416, -62.573) reference; L34 (55.216, -25.223)-(55.216, -59.922); C1 r 3.65 at (55.216, -83.573) reference; C2 r 3.65 at (79.806, 116.427) reference; C3 r 3.65 at (30.626, 116.427) reference; C4 r 1.75 at (23.726, 39.573) reference; C5 r 1.75 at (23.726, 75.427) reference; C6 r 1.75 at (51.726, 39.573) reference; C7 r 3.65 at (55.216, 116.427) reference; C8 r 3.65 at (30.626, -83.573) reference; C9 r 3.65 at (79.806, -83.573) reference; C10 r 1.65 at (55.216, -25.223); C11 r 1.65 at (55.216, -59.922); A1 r 1.75 centre (51.726, 75.427) between (53.016, 76.61) and (53.016, 74.245) reference; 4 further points
  constraints: 3 midpoint, 2 centre point, 2 end point, 1 coincident, 1 equal radius, 1 horizontal alignment, 1 vertical, 1 vertical alignment
  dimensions: "d281" = 3.3 diameter of C11; "d282" = 1 distance edge to line of C10 L32
extrude "Выдавливание36" cut sketch "Эскиз46" distance "d283" = 10; taper "d284" = 0 deg
chamfer "Фаска14" distance "d286" = 2.5; stored, may be unused: second distance "d287" = 2, angle "d288" = 45 deg
sketch "Эскиз47"
  geometry: L1 (-87.5, 0)-(0, 0) reference; L2 (0, 0)-(0, 5) reference; L3 (-87.5, 5)-(0, 5) reference; L4 (-87.5, 0)-(-87.5, 5) reference; L5 (-87.5, 5)-(0, 5); L6 (0, 5)-(0, -20.518); L7 (0, -20.518)-(-87.5, -20.518); L8 (-87.5, -20.518)-(-87.5, 5); 3 further points
  constraints: 8 end point, 2 parallel, 1 horizontal, 1 perpendicular
extrude "Выдавливание37" sketch "Эскиз47" distance "d293" = 500; taper "d294" = 0 deg
feature "ཏ耀ད耀ན耀ཕ耀བྷ耀ཙ耀ཛ耀ཝ耀" dims "d0" = 16, "d1" = 200, "d2" = 200, "d3" = 0, "d4" = 24.6, "d5" = 11, "d6" = 0, "d7" = 8, "d8" = 6, "d9" = 0, "d10" = 4, "d11" = 0, "d12" = 2.5, "d13" = 2.5 (= d12), "d14" = 3.2 (derived), "d15" = 3.2 (derived), "d16" = 3.2, "d17" = 5, "d18" = 0, "d19" = 5, "d20" = 2, "d21" = 2, "d22" = 45 deg, "d23" = 5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
node "Твердое тело1"
node "Твердое тело2"
node "Спроецированная петля1"
node "Спроецированная петля2"
node "Спроецированная петля3"
node "Спроецированная петля4"
node "Каретка"
node "Спроецированная петля8"
node "Рука"
node "Спроецированная петля10"
node "Основная плита"
node "Крепление"
node "Спроецированная петля12"
node "Спроецированная петля13"
node "Эскиз — прямоугольный массив1" dims "d85" = 24.58984 (derived), "d88" = 10
node "Спроецированная петля14"
node "Эскиз — прямоугольный массив2" dims "d101" = 24.58984 (derived), "d104" = 10
node "Спроецированная петля15"
node "Эскиз — прямоугольный массив3" dims "d116" = 59 (derived), "d119" = 10
node "Спроецированная петля16"
node "Ребро жесткости"
node "Спроецированная петля17"
node "Спроецированная петля18"
node "Спроецированная петля19"
node "Спроецированная петля20"
node "Спроецированная петля21"
node "Спроецированная петля22"
node "Эскиз — прямоугольный массив4" dims "d172" = 24.58984 (derived), "d175" = 10
node "Спроецированная петля23"
node "Спроецированная петля24"
node "Спроецированная петля25"
node "Спроецированная петля26"
node "Спроецированная петля27"
node "Спроецированная петля28"
node "Спроецированная петля29"
node "Спроецированная петля30"
node "Спроецированная петля31"
node "Спроецированная петля32"
node "Спроецированная петля33"
node "Стойки под колеса"
node "Колеса"
node "Эскиз — прямоугольный массив5" dims "d244" = 35.855 (derived), "d247" = 28 (derived)
node "Твердое тело13"
node "Спроецированная петля34"
node "Спроецированная петля35"
node "Спроецированная петля36"
